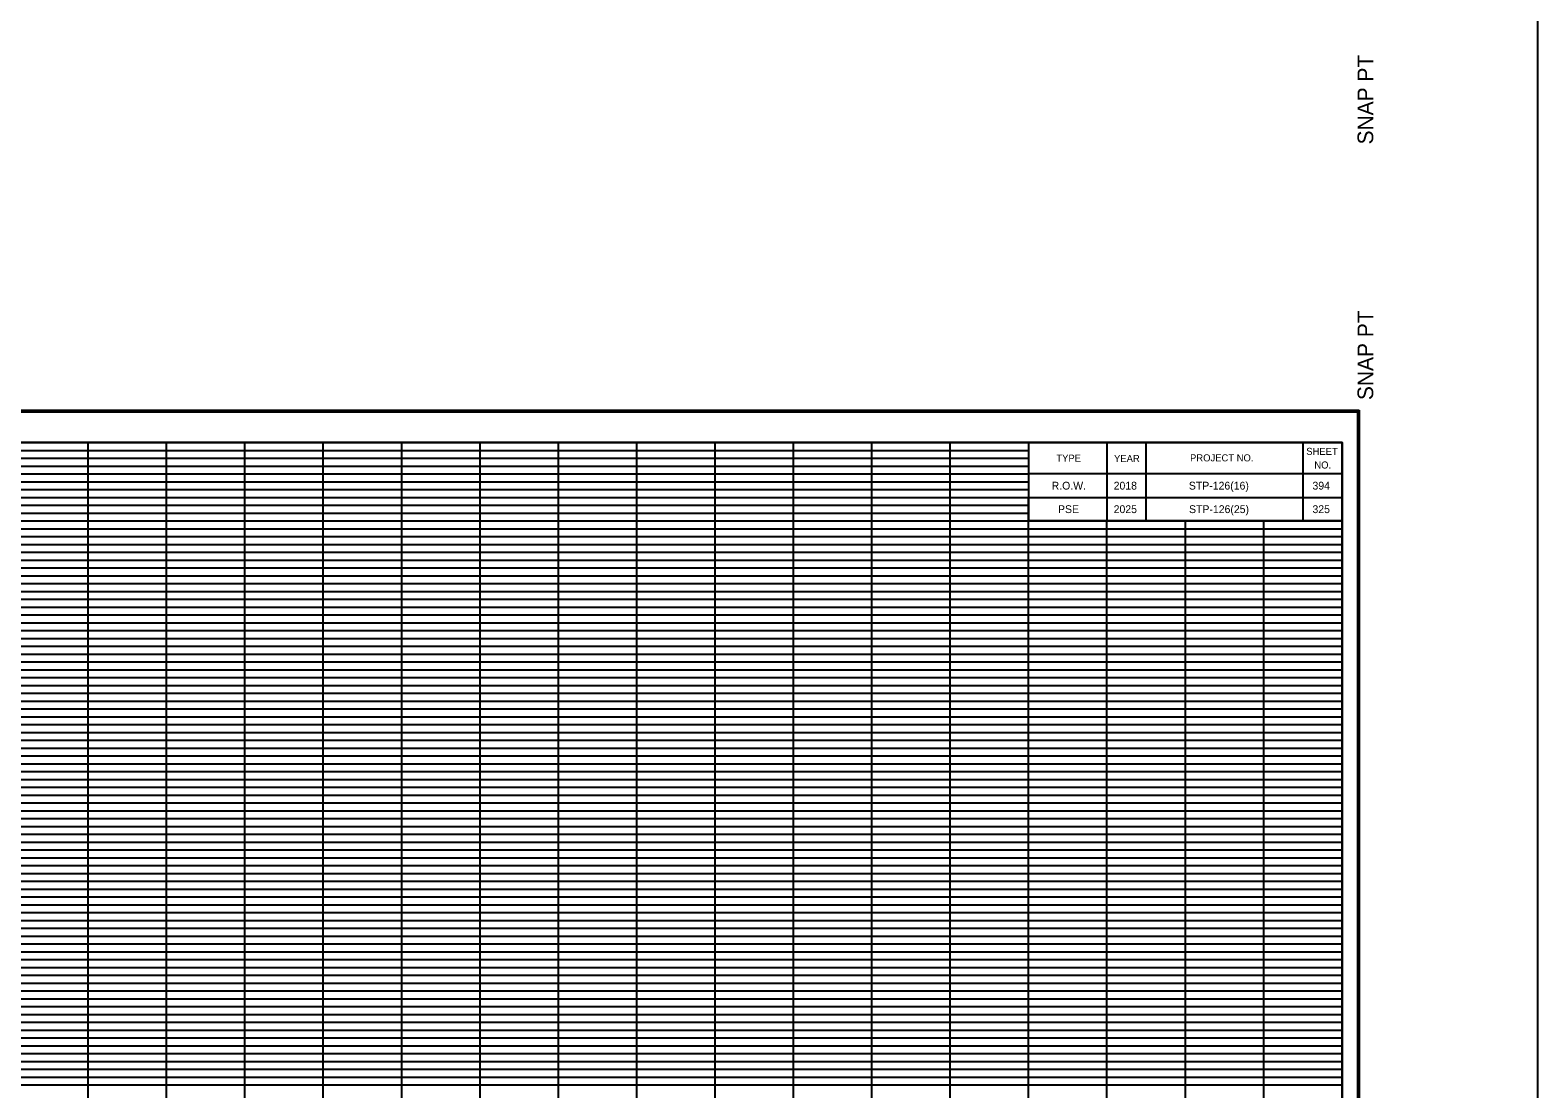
# Model space of a CAD drawing. Extents: x 955 to 1375, y 1248 to 3657.
# Drawn here: x 1152.6 to 1345, y 1937.5 to 2072.7 of the extents above; entities that cross this region are included whole.
import ezdxf

# ---------------------------------------------------------------- set-up
doc = ezdxf.new("R2010")
doc.units = 0
for name, color, linetype in [('DESIGN - SCRATCH - User 1', 7, 'Continuous'), ('DESIGN - SHEET - Corner Text', 7, 'Continuous'), ('DESIGN - SHEET - Light Grid', 7, 'Continuous'), ('DESIGN - SHEET - Linework', 7, 'Continuous'), ('DESIGN - SHEET - Plot Shape', 7, 'Continuous'), ('DESIGN - UTILITIES - Cable (Overhead) with Text', 7, 'Continuous'), ('SURVEY - NON-TRANSPORTATION - Features Text', 7, 'Continuous')]:
    doc.layers.add(name, color=color, linetype=linetype)

# ---------------------------------------------------------------- blocks, each defined once
blk = doc.blocks.new('XSTSHT')
at = {"layer": 'DESIGN - SCRATCH - User 1'}
for p, q in [((28.5, 20.45), (28.5, 20.45)), ((29.24, 20.45), (29.24, 20.45)), ((30.49, 20.45), (30.49, 20.45)), ((31.74, 20.45), (31.74, 20.45)), ((28.5, 20.15), (28.5, 20.15)), ((29.24, 20.15), (29.24, 20.15)), ((30.49, 20.15), (30.49, 20.15)), ((31.74, 20.15), (31.74, 20.15))]:
    blk.add_line(p, q, dxfattribs=at)
at = {"layer": 'DESIGN - SHEET - Light Grid'}
for p, q in [((8, 20.9), (16, 20.9)), ((8, 20.8), (16, 20.8)), ((16, 20.9), (24, 20.9)), ((16, 20.8), (24, 20.8)), ((24, 20.9), (28, 20.9)), ((24, 20.8), (28, 20.8)), ((8, 20.7), (16, 20.7)), ((8, 20.6), (16, 20.6)), ((16, 20.7), (24, 20.7)), ((16, 20.6), (24, 20.6)), ((24, 20.7), (28, 20.7)), ((24, 20.6), (28, 20.6)), ((8, 20.5), (16, 20.5)), ((8, 20.4), (16, 20.4)), ((16, 20.5), (24, 20.5)), ((16, 20.4), (24, 20.4)), ((24, 20.5), (28, 20.5)), ((24, 20.4), (28, 20.4)), ((8, 20.3), (16, 20.3)), ((16, 20.3), (24, 20.3)), ((24, 20.3), (28, 20.3)), ((8, 20.2), (16, 20.2)), ((8, 20.1), (16, 20.1)), ((16, 20.2), (24, 20.2)), ((16, 20.1), (24, 20.1)), ((24, 20.2), (28, 20.2)), ((24, 20.1), (28, 20.1)), ((8, 19.9), (16, 19.9)), ((16, 19.9), (24, 19.9)), ((24, 19.9), (32, 19.9)), ((8, 19.8), (16, 19.8)), ((8, 19.7), (16, 19.7)), ((16, 19.8), (24, 19.8)), ((16, 19.7), (24, 19.7)), ((24, 19.8), (32, 19.8)), ((24, 19.7), (32, 19.7)), ((8, 19.6), (16, 19.6)), ((8, 19.5), (16, 19.5)), ((16, 19.6), (24, 19.6)), ((16, 19.5), (24, 19.5)), ((24, 19.6), (32, 19.6)), ((24, 19.5), (32, 19.5)), ((8, 19.4), (16, 19.4)), ((8, 19.3), (16, 19.3)), ((16, 19.4), (24, 19.4)), ((16, 19.3), (24, 19.3)), ((24, 19.4), (32, 19.4)), ((24, 19.3), (32, 19.3)), ((8, 19.2), (16, 19.2)), ((8, 19.1), (16, 19.1)), ((16, 19.2), (24, 19.2)), ((16, 19.1), (24, 19.1)), ((24, 19.2), (32, 19.2)), ((24, 19.1), (32, 19.1)), ((8, 18.9), (16, 18.9)), ((16, 18.9), (24, 18.9)), ((24, 18.9), (32, 18.9)), ((8, 18.8), (16, 18.8)), ((8, 18.7), (16, 18.7)), ((16, 18.8), (24, 18.8)), ((16, 18.7), (24, 18.7)), ((24, 18.8), (32, 18.8)), ((24, 18.7), (32, 18.7)), ((8, 18.6), (16, 18.6)), ((8, 18.5), (16, 18.5)), ((16, 18.6), (24, 18.6)), ((16, 18.5), (24, 18.5)), ((24, 18.6), (32, 18.6)), ((24, 18.5), (32, 18.5)), ((8, 18.4), (16, 18.4)), ((8, 18.3), (16, 18.3)), ((16, 18.4), (24, 18.4)), ((16, 18.3), (24, 18.3)), ((24, 18.4), (32, 18.4)), ((24, 18.3), (32, 18.3)), ((8, 18.2), (16, 18.2)), ((8, 18.1), (16, 18.1)), ((16, 18.2), (24, 18.2)), ((16, 18.1), (24, 18.1)), ((24, 18.2), (32, 18.2)), ((24, 18.1), (32, 18.1)), ((8, 17.9), (16, 17.9)), ((16, 17.9), (24, 17.9)), ((24, 17.9), (32, 17.9)), ((8, 17.8), (16, 17.8)), ((8, 17.7), (16, 17.7)), ((16, 17.8), (24, 17.8)), ((16, 17.7), (24, 17.7)), ((24, 17.8), (32, 17.8)), ((24, 17.7), (32, 17.7)), ((8, 17.6), (16, 17.6)), ((16, 17.6), (24, 17.6)), ((24, 17.6), (32, 17.6)), ((8, 17.5), (16, 17.5)), ((8, 17.4), (16, 17.4)), ((16, 17.5), (24, 17.5)), ((16, 17.4), (24, 17.4)), ((24, 17.5), (32, 17.5)), ((24, 17.4), (32, 17.4)), ((8, 17.3), (16, 17.3)), ((8, 17.2), (16, 17.2)), ((16, 17.3), (24, 17.3)), ((16, 17.2), (24, 17.2)), ((24, 17.3), (32, 17.3)), ((24, 17.2), (32, 17.2)), ((8, 17.1), (16, 17.1)), ((16, 17.1), (24, 17.1)), ((24, 17.1), (32, 17.1)), ((8, 16.9), (16, 16.9)), ((8, 16.8), (16, 16.8)), ((16, 16.9), (24, 16.9)), ((16, 16.8), (24, 16.8)), ((24, 16.9), (32, 16.9)), ((24, 16.8), (32, 16.8)), ((8, 16.7), (16, 16.7)), ((8, 16.6), (16, 16.6)), ((16, 16.7), (24, 16.7)), ((16, 16.6), (24, 16.6)), ((24, 16.7), (32, 16.7)), ((24, 16.6), (32, 16.6)), ((8, 16.5), (16, 16.5)), ((8, 16.4), (16, 16.4)), ((16, 16.5), (24, 16.5)), ((16, 16.4), (24, 16.4)), ((24, 16.5), (32, 16.5)), ((24, 16.4), (32, 16.4)), ((8, 16.3), (16, 16.3)), ((8, 16.2), (16, 16.2)), ((16, 16.3), (24, 16.3)), ((16, 16.2), (24, 16.2)), ((24, 16.3), (32, 16.3)), ((24, 16.2), (32, 16.2)), ((8, 16.1), (16, 16.1)), ((16, 16.1), (24, 16.1)), ((24, 16.1), (32, 16.1)), ((8, 15.9), (16, 15.9)), ((8, 15.8), (16, 15.8)), ((16, 15.9), (24, 15.9)), ((16, 15.8), (24, 15.8)), ((24, 15.9), (32, 15.9)), ((24, 15.8), (32, 15.8)), ((8, 15.7), (16, 15.7)), ((8, 15.6), (16, 15.6)), ((16, 15.7), (24, 15.7)), ((16, 15.6), (24, 15.6)), ((24, 15.7), (32, 15.7)), ((24, 15.6), (32, 15.6)), ((8, 15.5), (16, 15.5)), ((8, 15.4), (16, 15.4)), ((16, 15.5), (24, 15.5)), ((16, 15.4), (24, 15.4)), ((24, 15.5), (32, 15.5)), ((24, 15.4), (32, 15.4)), ((8, 15.3), (16, 15.3)), ((8, 15.2), (16, 15.2)), ((16, 15.3), (24, 15.3)), ((16, 15.2), (24, 15.2)), ((24, 15.3), (32, 15.3)), ((24, 15.2), (32, 15.2)), ((8, 15.1), (16, 15.1)), ((16, 15.1), (24, 15.1)), ((24, 15.1), (32, 15.1)), ((8, 14.9), (16, 14.9)), ((16, 14.9), (24, 14.9)), ((24, 14.9), (32, 14.9)), ((8, 14.8), (16, 14.8)), ((8, 14.7), (16, 14.7)), ((16, 14.8), (24, 14.8)), ((16, 14.7), (24, 14.7)), ((24, 14.8), (32, 14.8)), ((24, 14.7), (32, 14.7)), ((8, 14.6), (16, 14.6)), ((8, 14.5), (16, 14.5)), ((16, 14.6), (24, 14.6)), ((16, 14.5), (24, 14.5)), ((24, 14.6), (32, 14.6)), ((24, 14.5), (32, 14.5)), ((8, 14.4), (16, 14.4)), ((8, 14.3), (16, 14.3)), ((16, 14.4), (24, 14.4)), ((16, 14.3), (24, 14.3)), ((24, 14.4), (32, 14.4)), ((24, 14.3), (32, 14.3)), ((8, 14.2), (16, 14.2)), ((8, 14.1), (16, 14.1)), ((16, 14.2), (24, 14.2)), ((16, 14.1), (24, 14.1)), ((24, 14.2), (32, 14.2)), ((24, 14.1), (32, 14.1)), ((8, 13.9), (16, 13.9)), ((16, 13.9), (24, 13.9)), ((24, 13.9), (32, 13.9)), ((8, 13.8), (16, 13.8)), ((8, 13.7), (16, 13.7)), ((16, 13.8), (24, 13.8)), ((16, 13.7), (24, 13.7)), ((24, 13.8), (32, 13.8)), ((24, 13.7), (32, 13.7)), ((8, 13.6), (16, 13.6)), ((8, 13.5), (16, 13.5)), ((16, 13.6), (24, 13.6)), ((16, 13.5), (24, 13.5)), ((24, 13.6), (32, 13.6)), ((24, 13.5), (32, 13.5)), ((8, 13.4), (16, 13.4)), ((8, 13.3), (16, 13.3)), ((16, 13.4), (24, 13.4)), ((16, 13.3), (24, 13.3)), ((24, 13.4), (32, 13.4)), ((24, 13.3), (32, 13.3)), ((8, 13.2), (16, 13.2)), ((8, 13.1), (16, 13.1)), ((16, 13.2), (24, 13.2)), ((16, 13.1), (24, 13.1)), ((24, 13.2), (32, 13.2)), ((24, 13.1), (32, 13.1)), ((8, 12.9), (16, 12.9)), ((16, 12.9), (24, 12.9)), ((24, 12.9), (32, 12.9)), ((8, 12.8), (16, 12.8)), ((16, 12.8), (24, 12.8)), ((24, 12.8), (32, 12.8))]:
    blk.add_line(p, q, dxfattribs=at)
at = {"layer": 'DESIGN - SHEET - Linework'}
for p, q in [((-1.823, 21.414), (32.217, 21.414)), ((32.217, 21.414), (32.217, -0.414)), ((16, 0), (16, 21)), ((17, 0), (17, 21)), ((18, 0), (18, 21)), ((19, 0), (19, 21)), ((20, 0), (20, 21)), ((21, 0), (21, 21)), ((22, 0), (22, 21)), ((23, 0), (23, 21)), ((24, 0), (24, 21)), ((25, 0), (25, 21)), ((26, 0), (26, 21)), ((27, 0), (27, 21)), ((0, 20), (28, 20)), ((28, 0), (28, 20)), ((29, 0), (29, 20)), ((30, 0), (30, 20)), ((31, 0), (31, 20)), ((0, 19), (32, 19)), ((0, 18), (32, 18)), ((0, 17), (32, 17)), ((0, 16), (32, 16)), ((0, 15), (32, 15)), ((0, 14), (32, 14)), ((0, 13), (32, 13))]:
    blk.add_line(p, q, dxfattribs=at)
for points in [[(0, 21), (0, 0), (32, 0), (32, 21), (0, 21)], [(28, 21), (28, 20), (32, 20), (32, 21), (31.5, 21), (31.5, 20), (29.5, 20), (29.5, 21), (29, 21), (29, 20), (32, 20), (28, 20), (28, 20.3), (32, 20.3), (32, 20.6), (28, 20.6)]]:
    blk.add_lwpolyline(points, dxfattribs=at)
at = {"layer": 'DESIGN - SHEET - Plot Shape'}
for points in [[(-1.803, 21.394), (32.197, 21.394), (32.197, -0.394), (-1.803, -0.394)], [(-0.85, 21), (32, 21), (32, -0.25), (-0.85, -0.25)]]:
    blk.add_lwpolyline(points, close=True, dxfattribs=at)
at = {"layer": 'DESIGN - SHEET - Corner Text'}
for s, p in [('  SNAP PT', (32.397, 21.394)), ('SNAP PT  ', (32.397, -2.194))]:
    blk.add_text(s, height=0.2, rotation=90, dxfattribs=at).set_placement(p)
for s, p in [('TYPE', (28.354, 20.756)), ('YEAR', (29.09, 20.752)), ('PROJECT NO.', (30.06, 20.76)), ('SHEET', (31.543, 20.843)), ('NO.', (31.646, 20.669))]:
    blk.add_text(s, height=0.09, dxfattribs=at).set_placement(p)

msp = doc.modelspace()

# ---------------------------------------------------------------- linework, layer by layer
at = {"layer": 'DESIGN - SHEET - Plot Shape'}
msp.add_lwpolyline([(991.5, 1807.5), (1320, 1807.5), (1320, 2020), (991.5, 2020)], close=True, dxfattribs=at)
at = {"layer": 'SURVEY - NON-TRANSPORTATION - Features Text'}
msp.add_lwpolyline([(955.41, 1505.76), (1344.98, 1505.76), (1344.98, 3398.01), (955.41, 3398.01)], close=True, dxfattribs=at)

# ---------------------------------------------------------------- block references
at = {"layer": 'DESIGN - UTILITIES - Cable (Overhead) with Text', "xscale": 10, "yscale": 10}
for p in [(1000, 2080), (1000, 1810)]:
    msp.add_blockref('XSTSHT', p, dxfattribs=at)

# ---------------------------------------------------------------- texts
at = {"layer": 'DESIGN - SHEET - Corner Text'}
for s, p in [('R.O.W.', (1282.94, 2014)), ('2018', (1290.85, 2014)), ('STP-126(16)', (1300.45, 2014)), ('394', (1316.22, 2014)), ('PSE', (1283.75, 2011)), ('2025', (1290.85, 2011)), ('STP-126(25)', (1300.47, 2011)), ('325', (1316.22, 2011))]:
    msp.add_text(s, height=1, dxfattribs=at).set_placement(p)

doc.saveas('drawing.dxf')
